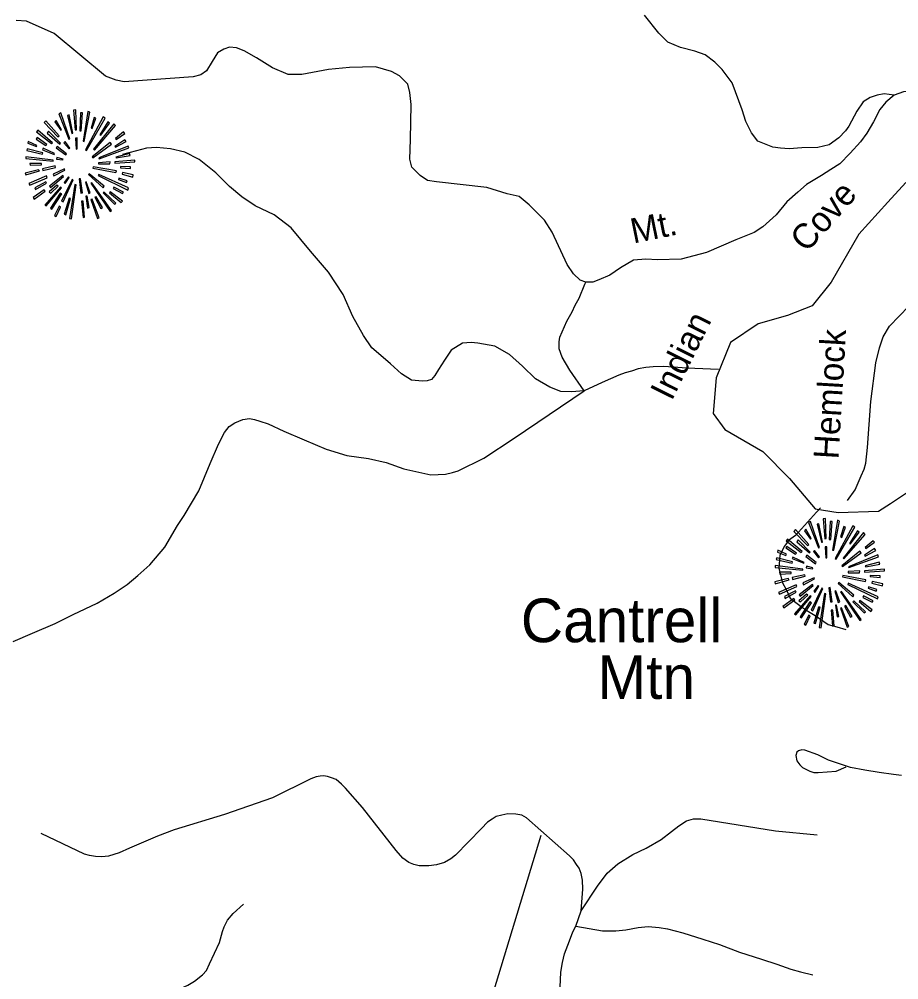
# Model space of a CAD drawing. Extents: x 884530 to 1028605, y 526725 to 653634.
# Drawn here: x 946966 to 949276, y 580476 to 583000 of the extents above; entities that cross this region are included whole.
import ezdxf

# ---------------------------------------------------------------- set-up
doc = ezdxf.new("R2010")
doc.units = 0
for name, color, linetype in [('Exist Geographical Mountain Summit CELL', 7, 'Continuous'), ('Exist Geographical Mountain Summit Label', 7, 'Continuous'), ('Exist Hydrographic Creek Single Shore', 7, 'Continuous'), ('Exist Road Non-System Type 51', 7, 'Continuous'), ('Exist Road Non-System Type 51 Label', 7, 'Continuous'), ('Exist Road Secondary Type 41 Attributed', 7, 'Continuous'), ('Exist Road Secondary Type 51 Label', 7, 'Continuous')]:
    doc.layers.add(name, color=color, linetype=linetype)

msp = doc.modelspace()

# ---------------------------------------------------------------- linework, layer by layer
at = {"layer": 'Exist Geographical Mountain Summit CELL'}
for points in [[(947109, 582760.9), (947113, 582708.9), (947116.2, 582709.3), (947114.8, 582762)], [(947059.5, 582729.7), (947075.1, 582707.9), (947077, 582709.3), (947063.5, 582733.7)], [(947070.4, 582751.5), (947096.6, 582684.6), (947099.5, 582685.7), (947075.5, 582754)], [(947104.2, 582699.5), (947106.8, 582700.2), (947097.7, 582748.2), (947093.3, 582747.1)], [(947125, 582706.8), (947128.9, 582706.8), (947132.5, 582754), (947127.1, 582754)], [(947136.9, 582678.4), (947151.8, 582755.5), (947146.4, 582757.3), (947133.7, 582679.2)], [(947140.2, 582656.6), (947143.1, 582654.8), (947191.8, 582739.5), (947186.3, 582743.1)], [(947154.7, 582713.7), (947158, 582712.5), (947167.5, 582739.5), (947162.7, 582741.3)], [(947031.9, 582728.2), (947067.9, 582690.8), (947071.2, 582693.3), (947035.9, 582733)], [(947161.3, 582658.1), (947163.5, 582655.9), (947219, 582720.2), (947215, 582725)], [(947198.7, 582729.7), (947177.6, 582696.2), (947180.6, 582695.1), (947203, 582726.4)], [(947010.5, 582684.6), (947036.3, 582668.2), (947038.5, 582670.8), (947013.4, 582688.6)], [(947011.6, 582703.5), (947051.2, 582673), (947053.4, 582675.2), (947015.2, 582707.9)], [(947039.9, 582700.6), (947072.6, 582671.5), (947074.8, 582673.7), (947042.8, 582705.7)], [(947114.4, 582687.5), (947115.8, 582658.4), (947118.4, 582658.8), (947118.4, 582687.9)], [(947219, 582663.2), (947246.6, 582678.1), (947243.8, 582683.1), (947217.6, 582665.7)], [(947219, 582686.1), (947220.9, 582683.5), (947243.8, 582699.8), (947240.1, 582703.5)], [(946985.8, 582654.4), (947027.2, 582645), (947028.3, 582648.3), (946986.9, 582659.2)], [(946988.7, 582673.7), (947011.2, 582665), (947012.3, 582667.9), (946990.1, 582678.8)], [(947027.2, 582656.6), (947057.7, 582644.7), (947058.8, 582646.8), (947029.4, 582660.7)], [(947063.5, 582662.1), (947088.6, 582643.1), (947090.7, 582646.1), (947066.1, 582665.3)], [(947083.2, 582675.2), (947097, 582658.8), (947099.1, 582661), (947086.4, 582678.1)], [(947158, 582638.1), (947159.8, 582635.6), (947208.5, 582671.5), (947205.3, 582675.9)], [(947175, 582635.2), (947176.2, 582633), (947254.3, 582661.7), (947252.5, 582666.4)], [(946983.2, 582633.4), (947055.2, 582626.4), (947055.5, 582629.4), (946983.2, 582638.4)], [(947063.9, 582632.3), (947081, 582630.1), (947081.4, 582632.3), (947064.6, 582636.6)], [(947220.9, 582635.2), (947257.6, 582641.7), (947256.1, 582647.2), (947219.5, 582637.4)], [(946995.3, 582615.9), (947025, 582617.4), (947025, 582621), (946994.1, 582621)], [(947027.6, 582606.9), (947028.6, 582602.1), (947061.7, 582610.5), (947061, 582614.1)], [(947159.4, 582608.7), (947220.2, 582596.7), (947221.3, 582601), (947160.5, 582612.3)], [(947174, 582622.5), (947174, 582619.6), (947204.2, 582619.6), (947204.9, 582624.6)], [(947217.2, 582621.4), (947269.6, 582624.6), (947269.9, 582629.4), (947217.6, 582624.6)], [(947232.1, 582609.4), (947258.7, 582607.2), (947258.7, 582611.5), (947232.5, 582612.6)], [(946981.8, 582595.6), (946983.2, 582590.5), (947019.2, 582601), (947017, 582604.3)], [(946991.5, 582567.9), (946994.1, 582563.3), (947039.5, 582583.2), (947038.1, 582587.9)], [(947045.3, 582561.4), (947048.2, 582557.7), (947082.8, 582586.1), (947081, 582588.7)], [(947055.2, 582592.7), (947057.4, 582587.9), (947086.1, 582603.2), (947085, 582606.5)], [(947083.9, 582570.8), (947087.1, 582567.9), (947097.3, 582584.3), (947095.5, 582585.7)], [(947148.2, 582591.6), (947186.7, 582556.3), (947189.3, 582560.7), (947150, 582593.8)], [(947173.2, 582589.1), (947251.4, 582550.9), (947253.2, 582556.3), (947174.8, 582592)], [(947226.7, 582578.9), (947247.8, 582570.8), (947249.6, 582575.2), (947228.1, 582582.1)], [(947236.2, 582592.3), (947264.5, 582585), (947265.2, 582590.5), (947237.2, 582596.7)], [(947009, 582552), (947038.1, 582568.7), (947035.9, 582572.3), (947006.8, 582557)], [(947033.7, 582511.6), (947036.6, 582509.1), (947077.4, 582556.7), (947074.4, 582558.8)], [(947049, 582542.9), (947068.3, 582561), (947064.9, 582563.3), (947044.6, 582546.1)], [(947077, 582521.5), (947081.4, 582519.7), (947107.9, 582578.1), (947105.3, 582578.9)], [(947098.4, 582476), (947103.1, 582474.9), (947115.8, 582564.3), (947112.6, 582565.1)], [(947123.9, 582580), (947127.8, 582542.9), (947132.2, 582543.2), (947127.1, 582580.7)], [(947139.9, 582571.2), (947148.6, 582541.4), (947152.6, 582543.2), (947142, 582572.3)], [(947154.4, 582569), (947204.9, 582494.2), (947208.5, 582497.1), (947156.9, 582570.1)], [(947212.5, 582554.9), (947237.6, 582541.8), (947240.1, 582545.5), (947214.7, 582558.8)], [(947002.8, 582531.2), (947005.7, 582527.2), (947034.1, 582548.3), (947031.5, 582551.6)], [(947073.7, 582542.9), (947048.6, 582503.6), (947051.8, 582501.1), (947077.7, 582540.7)], [(947149.6, 582504.7), (947144.2, 582534.6), (947140.9, 582534.6), (947145.3, 582503.6)], [(947164.9, 582532), (947180.9, 582502.5), (947184.9, 582504.7), (947168.6, 582533.4)], [(947186.7, 582543.2), (947216.8, 582514.1), (947220.2, 582516.7), (947188.9, 582545.7)], [(947203.4, 582543.9), (947233.9, 582518.1), (947237.2, 582521.8), (947205.3, 582546.5)], [(947058.8, 582484.4), (947063.5, 582481.5), (947074.4, 582506.2), (947071.2, 582508.4)], [(947088.6, 582486.2), (947100.6, 582529), (947097, 582529.4), (947084.2, 582487.2)], [(947130, 582521.5), (947133.7, 582479), (947137.7, 582480), (947134.3, 582521.5)], [(947154.4, 582526.2), (947171.8, 582476.4), (947176.2, 582478.2), (947157.3, 582526.9)], [(949038.6, 581677.6), (949064.8, 581610.7), (949067.8, 581611.7), (949043.8, 581680.1)], [(949072.5, 581625.6), (949075, 581626.3), (949066, 581674.2), (949061.6, 581673.2)], [(949077.2, 581687), (949081.3, 581635), (949084.5, 581635.4), (949083.1, 581688.1)], [(949093.2, 581632.9), (949097.2, 581632.9), (949100.8, 581680.1), (949095.3, 581680.1)], [(949105.2, 581604.5), (949120.1, 581681.5), (949114.6, 581683.3), (949101.9, 581605.2)], [(949000.2, 581654.3), (949036.1, 581616.9), (949039.4, 581619.4), (949004.2, 581659)], [(949027.7, 581655.7), (949043.4, 581634), (949045.2, 581635.4), (949031.8, 581659.7)], [(949108.4, 581582.7), (949111.4, 581580.9), (949160, 581665.5), (949154.6, 581669.2)], [(949122.9, 581639.7), (949126.3, 581638.6), (949135.7, 581665.5), (949131, 581667.3)], [(949129.5, 581584.1), (949131.7, 581582), (949187.3, 581646.2), (949183.3, 581651)], [(949167, 581655.7), (949145.9, 581622.3), (949148.8, 581621.2), (949171.3, 581652.5)], [(948979.8, 581629.5), (949019.4, 581599), (949021.6, 581601.2), (948983.5, 581634)], [(949008.1, 581626.6), (949040.8, 581597.6), (949043, 581599.7), (949011, 581631.7)], [(949187.3, 581612.1), (949189.1, 581609.6), (949212, 581625.9), (949208.4, 581629.5)], [(948956.9, 581599.7), (948979.4, 581591.1), (948980.5, 581594), (948958.4, 581604.9)], [(948978.7, 581610.7), (949004.5, 581594.3), (949006.7, 581596.9), (948981.6, 581614.6)], [(949051.4, 581601.2), (949065.2, 581584.8), (949067.4, 581587), (949054.7, 581604.2)], [(949082.7, 581613.6), (949084.1, 581584.5), (949086.7, 581584.8), (949086.7, 581613.9)], [(949126.3, 581564.1), (949128.1, 581561.6), (949176.7, 581597.6), (949173.5, 581602)], [(949187.3, 581589.3), (949214.9, 581604.2), (949212, 581609.2), (949185.9, 581591.8)], [(948954, 581580.5), (948995.4, 581571), (948996.5, 581574.3), (948955.1, 581585.2)], [(948995.4, 581582.7), (949025.9, 581570.7), (949027.1, 581572.8), (948997.6, 581586.7)], [(949031.8, 581588.1), (949056.9, 581569.2), (949059, 581572.1), (949034.3, 581591.4)], [(949143.3, 581561.3), (949144.4, 581559), (949222.5, 581587.7), (949220.7, 581592.5)], [(949189.1, 581561.3), (949225.9, 581567.8), (949224.4, 581573.2), (949187.7, 581563.5)], [(948951.4, 581559.4), (949023.4, 581552.5), (949023.7, 581555.4), (948951.4, 581564.5)], [(949032.1, 581558.3), (949049.2, 581556.1), (949049.6, 581558.3), (949032.9, 581562.7)], [(949142.3, 581548.6), (949142.3, 581545.6), (949172.4, 581545.6), (949173.1, 581550.7)], [(949185.5, 581547.4), (949237.8, 581550.7), (949238.2, 581555.4), (949185.9, 581550.7)], [(948950, 581521.7), (948951.4, 581516.5), (948987.5, 581527.1), (948985.3, 581530.3)], [(948963.5, 581542), (948993.2, 581543.4), (948993.2, 581547), (948962.4, 581547)], [(948995.8, 581532.9), (948996.9, 581528.2), (949030, 581536.6), (949029.3, 581540.2)], [(949023.4, 581518.7), (949025.6, 581514), (949054.3, 581529.2), (949053.3, 581532.5)], [(949127.7, 581534.7), (949188.4, 581522.8), (949189.5, 581527.1), (949128.8, 581538.4)], [(949200.4, 581535.5), (949226.9, 581533.2), (949226.9, 581537.6), (949200.8, 581538.7)], [(949204.4, 581518.3), (949232.7, 581511.1), (949233.4, 581516.5), (949205.4, 581522.8)], [(948959.8, 581494), (948962.4, 581489.3), (949007.8, 581509.3), (949006.3, 581514)], [(948977.3, 581478), (949006.3, 581494.7), (949004.2, 581498.4), (948975.1, 581483.1)], [(949013.6, 581487.5), (949016.5, 581483.8), (949051, 581512.2), (949049.2, 581514.7)], [(949045.2, 581447.5), (949049.6, 581445.7), (949076.1, 581504.2), (949073.6, 581505)], [(949052.1, 581496.9), (949055.4, 581494), (949065.6, 581510.4), (949063.7, 581511.8)], [(949092.1, 581506), (949096.1, 581469), (949100.5, 581469.3), (949095.3, 581506.8)], [(949108.1, 581497.3), (949116.8, 581467.5), (949120.8, 581469.3), (949110.2, 581498.4)], [(949116.5, 581517.6), (949155, 581482.4), (949157.5, 581486.7), (949118.3, 581519.9)], [(949141.5, 581515.1), (949219.7, 581476.9), (949221.5, 581482.4), (949143, 581518)], [(949195, 581505), (949216, 581496.9), (949217.8, 581501.3), (949196.4, 581508.2)], [(948971.1, 581457.3), (948974, 581453.3), (949002.4, 581474.4), (948999.8, 581477.6)], [(949002, 581437.7), (949004.9, 581435.1), (949045.6, 581482.8), (949042.7, 581484.9)], [(949017.3, 581469), (949036.5, 581487.1), (949033.2, 581489.3), (949012.8, 581472.2)], [(949066.6, 581402.1), (949071.4, 581401), (949084.1, 581490.3), (949080.9, 581491.1)], [(949122.6, 581495.1), (949173.1, 581420.2), (949176.7, 581423.1), (949125.1, 581496.2)], [(949171.7, 581470), (949202.2, 581444.2), (949205.4, 581447.8), (949173.5, 581472.6)], [(949180.8, 581481), (949205.8, 581467.9), (949208.4, 581471.5), (949183, 581484.9)], [(949042, 581469), (949016.9, 581429.7), (949020.1, 581427.2), (949046, 581466.7)], [(949056.9, 581412.3), (949068.8, 581455.1), (949065.2, 581455.5), (949052.5, 581413.3)], [(949098.3, 581447.5), (949101.9, 581405), (949105.9, 581406), (949102.6, 581447.5)], [(949117.9, 581430.8), (949112.4, 581460.6), (949109.2, 581460.6), (949113.6, 581429.7)], [(949122.6, 581452.2), (949140.1, 581402.4), (949144.4, 581404.2), (949125.5, 581453)], [(949133.1, 581458), (949149.1, 581428.6), (949153.2, 581430.8), (949136.8, 581459.5)], [(949155, 581469.3), (949185.1, 581440.2), (949188.4, 581442.8), (949157.2, 581471.8)], [(949027.1, 581410.4), (949031.8, 581407.6), (949042.7, 581432.2), (949039.4, 581434.4)]]:
    msp.add_lwpolyline(points, close=True, dxfattribs=at)
at = {"layer": 'Exist Hydrographic Creek Single Shore'}
msp.add_lwpolyline([(947901, 579420.7), (948336.3, 580855.9)], dxfattribs=at)
at = {"layer": 'Exist Road Non-System Type 51'}
msp.add_line((948427.4, 580617), (948441.7, 580657.9), dxfattribs=at)
for points in [[(949693.4, 583028.6), (949546.9, 582915.2), (949513.2, 582875.3), (949483.5, 582823.1), (949462.2, 582800.9), (949436.5, 582789.8), (949415.1, 582787.1), (949355.3, 582804.1), (949323.9, 582810.8), (949288.2, 582808.8), (949263.3, 582799.8)], [(948454.2, 582309.3), (948439.4, 582314.2), (948421.4, 582330.6), (948404.9, 582355.2), (948365.5, 582440.4), (948345.5, 582472.1), (948305.4, 582512.2), (948278.7, 582533.9), (948247.1, 582540.6), (948193.6, 582557.2), (948061.9, 582572.2), (948038.5, 582575.6), (948018.5, 582589), (947996.8, 582610.6), (947991.8, 582632.3), (947993.4, 582684), (947995, 582775.9), (947992.1, 582807), (947986.8, 582829.2), (947965.1, 582850.9), (947943.5, 582862.5), (947901.6, 582874.2), (947833.3, 582872.5), (947778.2, 582867.6), (947708.5, 582854), (947672.7, 582854), (947631.6, 582871.8), (947589.1, 582898.5), (947556.9, 582917), (947536.6, 582924.4), (947518.1, 582926.2), (947503.3, 582920.7), (947486.4, 582911.3), (947472.6, 582888.6), (947458.2, 582864.5), (947442.8, 582853.5), (947423.1, 582848.1), (947242, 582834.9), (947221, 582839.7), (947192.5, 582849.9), (947057.9, 582962.5), (946985, 582994.1), (946958, 582996)], [(949263.3, 582799.8), (949237.6, 582803.6), (949218.4, 582800.3), (949200.4, 582794.3), (949182.2, 582782.6), (949165.5, 582758.2), (949144.2, 582718.9), (949135.9, 582706.3), (949118.3, 582687.7), (949092.7, 582669.7), (949062.7, 582662.6), (949021, 582661.5), (948987.5, 582659.1), (948965.4, 582660.9), (948944.7, 582663.8), (948905.8, 582678.9), (948888.8, 582700.8), (948874, 582731.4), (948864.8, 582761.5), (948837.9, 582832.6), (948811.8, 582868), (948792.7, 582887), (948766.9, 582905.9), (948740.5, 582915.5), (948702.6, 582925), (948669.4, 582939.2), (948645.6, 582963), (948607.5, 583010.5)], [(949263.3, 582799.8), (949241.5, 582781.8), (949226.1, 582762.6), (949209.2, 582730.4), (949191.7, 582700.3), (949174.7, 582677.3), (949148, 582647.8), (949121.1, 582619.4), (949097.6, 582604.6), (949072.5, 582589.3), (949033.1, 582565.8), (949010.2, 582545), (948981.8, 582519.9), (948953.9, 582486), (948918.9, 582454.2), (948895.8, 582439), (948847.9, 582419.8), (948770.7, 582386.5), (948704.5, 582368.9), (948642.3, 582367.8), (948611.6, 582369.5), (948578.8, 582366.7), (948544.9, 582346.5), (948516.5, 582327.4), (948488.1, 582314.8), (948472.2, 582308.8), (948454.2, 582309.3)], [(948449.4, 582023.8), (948416.4, 582020.7), (948388.5, 582021.3), (948359.5, 582033.3), (948321.9, 582055.1), (948287.5, 582088), (948253.5, 582119.1), (948214.7, 582140.9), (948170.5, 582148.6), (948152.4, 582150.5), (948130.3, 582148.5), (948100.2, 582130.1), (948083, 582104), (948066.9, 582079.8), (948057.3, 582064), (948048.5, 582053.4), (948037.5, 582049.4), (948024.8, 582049.1), (947996.3, 582051.7), (947969.8, 582068.2), (947940.7, 582094.8), (947915.9, 582116.3), (947891.7, 582136.8), (947870, 582168.5), (947841.7, 582218.5), (947816.7, 582276.9), (947778.2, 582335.3), (947731.4, 582390.7), (947679.9, 582451.9), (947635.7, 582485.4), (947585.6, 582509.2), (947551, 582533.1), (947518.7, 582560.5), (947482.1, 582596), (947438.8, 582630.9), (947400.7, 582650), (947363.7, 582659.5), (947326.7, 582663.1), (947300.4, 582660.8), (947274.2, 582653.5), (947253.9, 582648.8), (947237.2, 582644)], [(948449.4, 582023.8), (948412, 582077.8), (948391.9, 582112), (948383.8, 582134.1), (948383.8, 582152.2), (948385.9, 582164.3), (948391.9, 582178.4), (948404, 582206.6), (948418.1, 582230.7), (948426.2, 582248.9), (948436.2, 582267), (948451.5, 582303.7), (948454.2, 582309.3)], [(949140.5, 581735.8), (949161.4, 581763.6), (949176.7, 581800.3), (949184.4, 581817.7), (949188.9, 581833.7), (949193.3, 581874.5), (949201.8, 581995.4), (949215.4, 582096.8), (949225.2, 582136.7), (949234.9, 582165.1), (949250.9, 582193.5), (949302.3, 582245.7)], [(948802.6, 582079.5), (948739.8, 582081.9), (948706.8, 582083.8), (948684.3, 582085.6), (948657.7, 582087.5), (948630.3, 582086.9), (948611.5, 582084.4), (948591.6, 582081.2), (948573.4, 582075.5), (948557.1, 582070.4), (948540.9, 582064.3), (948496.8, 582045.5), (948449.4, 582023.8)], [(947505.1, 581914.1), (947517.7, 581929.9), (947532.5, 581939.8), (947553.2, 581948), (947571.2, 581951.2), (947583.8, 581948.5), (947598, 581944.1), (947619.7, 581937.1), (947660.9, 581917.9), (947714.7, 581894.4), (947771.8, 581869.8), (947826.6, 581853.9), (947882.9, 581845.7), (947929.8, 581834.8), (947976, 581818.4), (948046.8, 581803), (948085.2, 581804.2), (948104.1, 581808.9), (948118.4, 581813.7), (948185.7, 581846.3), (948265.6, 581899.1), (948449.4, 582023.8)], [(946950.2, 581364.6), (947001, 581387), (947060.6, 581412.7), (947107.6, 581435.7), (947171, 581465.7), (947215.3, 581492), (947249.3, 581514.5), (947277.8, 581538.3), (947309.4, 581566.4), (947348.7, 581612.8), (947381.5, 581669.7), (947399, 581696), (947437.8, 581760.4), (947467.8, 581832.7), (947489.8, 581883.4), (947505.1, 581914.1)], [(949069.7, 581716), (949059.5, 581704.4), (949004.7, 581643.5), (948985.6, 581630.3), (948975.3, 581615.4), (948962.9, 581591.9), (948960.4, 581556.8), (948970.5, 581519.1), (948979.6, 581501.6), (948990.3, 581478.5), (949005.1, 581467.6), (949023.2, 581453.9), (949038.3, 581443.8), (949055.8, 581433.7), (949089.8, 581409.5), (949112.9, 581403.1), (949136.7, 581396.7)], [(949283.1, 581013.1), (949261.7, 581015.9), (949223.9, 581020.9), (949186.2, 581026.6), (949148.8, 581034), (949091.2, 581053.1), (949062.9, 581067.3), (949028.6, 581079.9), (949021.4, 581080.3), (949012.5, 581078.1), (949007.8, 581074.5), (949004.9, 581065.3), (949008.1, 581051.8), (949015.4, 581040.6), (949022.8, 581033.6), (949042.4, 581024.8), (949052.8, 581021.3), (949063.8, 581021.3), (949111.1, 581024.8), (949137.4, 581035.6)], [(948441.7, 580657.9), (948445.7, 580714.7), (948444.9, 580738.1), (948442, 580755.6), (948436.2, 580769.4), (948429.7, 580779), (948421.7, 580791.3), (948410.7, 580802.2), (948298.3, 580901.5), (948286, 580908.4), (948269.9, 580911), (948248.8, 580912.4), (948233.4, 580908.8), (948218.9, 580905.1), (948207.9, 580898.6), (948195.8, 580890.6), (948180.2, 580874), (948111.3, 580803.8), (948099.4, 580794.3), (948082.8, 580784.8), (948061.8, 580778.6), (948041.6, 580776), (948016.6, 580776), (948002, 580778.9), (947989.5, 580784.8), (947973.8, 580796.1), (947955.6, 580815.7), (947867.7, 580928.6), (947823.2, 580979.9), (947812.3, 580990.4), (947798.7, 581002.3), (947785.7, 581007.1), (947775.5, 581010), (947765.4, 581011.8), (947756.6, 581011.2), (947745.8, 581009.4), (947731.6, 581004.1), (947631.1, 580954.7), (947505.1, 580910.2), (947372.6, 580870.4), (947329.2, 580853.8), (947256.1, 580822.2), (947228.2, 580809.8), (947200.9, 580801.4), (947183, 580799.1), (947166.3, 580800.2), (947150.3, 580802.6), (947137.8, 580806.2), (947023.7, 580860.3)], [(948441.7, 580657.9), (948484.3, 580722.1), (948509.8, 580756.3), (948538.3, 580781.1), (948577.7, 580805.9), (948612.1, 580821.9), (948651.4, 580845.3), (948679.1, 580865.7), (948698.1, 580881.1), (948718.5, 580894.2), (948737, 580899.1), (948756.1, 580898.9), (948952.2, 580867.4), (949061.6, 580856.7)], [(947042.9, 580344.8), (947286.4, 580418.8), (947381.8, 580450.1), (947408.6, 580462.3), (947426.8, 580472.3), (947447.5, 580489), (947458.2, 580500.5), (947465.8, 580518), (947491.7, 580574.5), (947500.2, 580602.9), (947503.9, 580615.7), (947513.1, 580633.3), (947527.6, 580650.1), (947555.1, 580675.3)], [(948377.4, 580292.8), (948381.5, 580338.4), (948388, 580496.6), (948392.4, 580521.4), (948398.3, 580544.1), (948411.4, 580579.1), (948420.1, 580602.4), (948427.4, 580617)], [(948427.4, 580617), (948497.4, 580605.3), (948532.5, 580605.3), (948558.7, 580607.5), (948591.5, 580613.4), (948617.8, 580616.3), (948646.3, 580614), (948668.1, 580610.5), (948709, 580599.5), (948760.8, 580582.7), (948804.6, 580568.9), (948857.8, 580549.2), (948915.2, 580530.1), (948955.5, 580517.1), (948992, 580503.9), (949017.5, 580497.4), (949049.6, 580489.3)]]:
    msp.add_lwpolyline(points, dxfattribs=at)
at = {"layer": 'Exist Road Secondary Type 41 Attributed'}
msp.add_lwpolyline([(949294.4, 582570.7), (949246.6, 582519.1), (949170.3, 582435), (949098.4, 582308.9), (949048.2, 582246.8), (948983.1, 582221), (948906.6, 582199.8), (948834, 582150.1), (948796, 582057.3), (948788.4, 581963.6), (948818.9, 581921.6), (948918.2, 581864.3), (948988.9, 581793.5), (949055.7, 581713.3), (949116.8, 581703.9), (949221.9, 581707.5), (949254.1, 581727.4), (949332.6, 581780.2)], dxfattribs=at)

# ---------------------------------------------------------------- texts
at = {"layer": 'Exist Geographical Mountain Summit Label'}
for s, p in [('Cantrell', (948283.3, 581363.1)), ('Mtn', (948484.5, 581214.1))]:
    msp.add_text(s, height=114.83, dxfattribs=at).set_placement(p)
at = {"layer": 'Exist Road Non-System Type 51 Label'}
for s, rotation, p in [('Mt.', 11.5148, (948578.5, 582410.2)), ('Hemlock', 86.6151, (949117.2, 581842.7))]:
    msp.add_text(s, height=65.62, rotation=rotation, dxfattribs=at).set_placement(p)
at = {"layer": 'Exist Road Secondary Type 51 Label'}
for s, rotation, p in [('Cove', 48.4617, (949033.7, 582384.4)), ('Indian', 63.6677, (948679.2, 581995))]:
    msp.add_text(s, height=65.62, rotation=rotation, dxfattribs=at).set_placement(p)

doc.saveas('drawing.dxf')
